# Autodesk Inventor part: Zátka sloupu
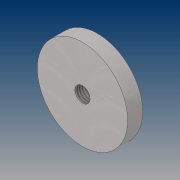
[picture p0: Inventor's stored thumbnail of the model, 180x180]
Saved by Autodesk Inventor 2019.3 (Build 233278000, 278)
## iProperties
Created: 2019-05
Part Number: Zátka sloupu
Material: Ocel, měkká, svařovaná
Document SubType Name: Modeling
Designer: B-hon
Density: 7.85 g/cm^3
Appearance: Svar – měkká ocel
Author: B-hon
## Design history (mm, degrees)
sketch "Náčrt1"
  geometry: C1 r 30 at (0, 0); 1 further point
  constraints: 1 centre point, 1 coincident
  dimensions: "d0" = 60 diameter of C1
extrude "Vysunutí1" new body sketch "Náčrt1" distance "d1" = 10; taper "d2" = 0 deg
sketch "Náčrt2"
  geometry: C1 r 30 at (0, 0) reference; 2 further points
  constraints: 1 coincident
hole "Díra1" sketch "Náčrt2" at (0, 0) diameter "d3" = 10.106; stored, may be unused: countersink angle "d7" = 90 deg, drill point angle "d9" = 118 deg; dims "d4" = 24, "d5" = 4, "d6" = 2, "d8" = 32.3
node "Těleso1"
